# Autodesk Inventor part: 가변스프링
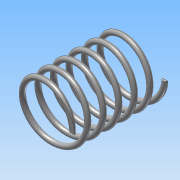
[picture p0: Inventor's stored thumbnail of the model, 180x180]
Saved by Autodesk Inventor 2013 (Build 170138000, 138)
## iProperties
Created: 2018-06
Part Number: 가변스프링
Material: 강철, 연강
Document SubType Name: Modeling
Designer: Administrator
Density: 7.86 g/cm^3
Mass: 82.8068 g
Surface Area: 106.473 cm^2
Volume: 10.5352 cm^3
Author: Administrator
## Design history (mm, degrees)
sketch "스케치1"
  geometry: L1 (0, 0)-(22.5, 0); L2 (0, 0)-(0, 73.25); L3 (0, 73.25)-(22.5, 73.25); C1 r 2 at (22.5, 0)
  constraints: 6 end point, 2 perpendicular, 1 centre point, 1 coincident, 1 horizontal
  dimensions: "d0" = 22.5 distance of L1.start L1.end; "d1" = 73.25 distance of L1.start L2.end (derived); "d2" = 22.5 distance of L2.end L3.end; "d3" = 4 diameter of C1
feature "코일1" sketch "스케치1" pitch "d4" = 10; turns "d6" = 6; dims "d5" = 73.25 (= d1), "d7" = 0, angle "d8" = 90 deg, angle "d9" = 90 deg, "d10" = 0, "d11" = 0
sketch "스케치2"
  geometry: L1 (73.25, 30)-(0, 30); L2 (0, 30)-(0, -30); L3 (0, -30)-(73.25, -30); L4 (73.25, -30)-(73.25, 30); 2 further points
  constraints: 8 end point, 2 parallel, 1 coincident, 1 horizontal, 1 midpoint, 1 perpendicular
  dimensions: "d12" = 60 distance of L3.end L1.start; "d15" = 73.25 distance of L2.end L3.end (derived)
extrude "돌출1" sketch "스케치2" stored distance "d16" = 10; taper "d17" = 0 deg
node "솔리드1"
